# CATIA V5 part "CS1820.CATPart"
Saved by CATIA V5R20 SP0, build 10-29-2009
Part number: CS1820
Revision: 3
Definition: design
Nomenclature: CS1820
Source: made
Description: NOT SPECIFIED
Bounding box of the stored display mesh (mm): x -18.807 to 19, y -19 to 19, z -36 to 9
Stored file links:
  C:\Users\Raffaele\Desktop\3D X SITO CF\BOLEX\20-TILTED COLUMN SUPPORT\CS1820.CATPart
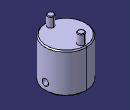
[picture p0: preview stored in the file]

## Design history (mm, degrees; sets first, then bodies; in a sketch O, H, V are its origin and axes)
Body1 "MANIFOLD_SOLID_BREP #695" (main body)
  Solid1: solid without history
